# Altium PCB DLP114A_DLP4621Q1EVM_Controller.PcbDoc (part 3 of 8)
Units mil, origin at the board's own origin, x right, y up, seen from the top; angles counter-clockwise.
Board outline 4803.15 x 2598.43 mil, 14 copper layers (Top Layer, GND 1, SIGNAL 1, GND 2, SIGNAL 2, PWR SPLIT PLANE 1, GND 3, GND 4, PWR SPLIT PLANE 2, SIGNAL 3, GND 5, SIGNAL 4, GND 6, Bottom Layer), stack 91.4 mil thick; 489 components, 394 nets, 1925 pads, 1273 vias.
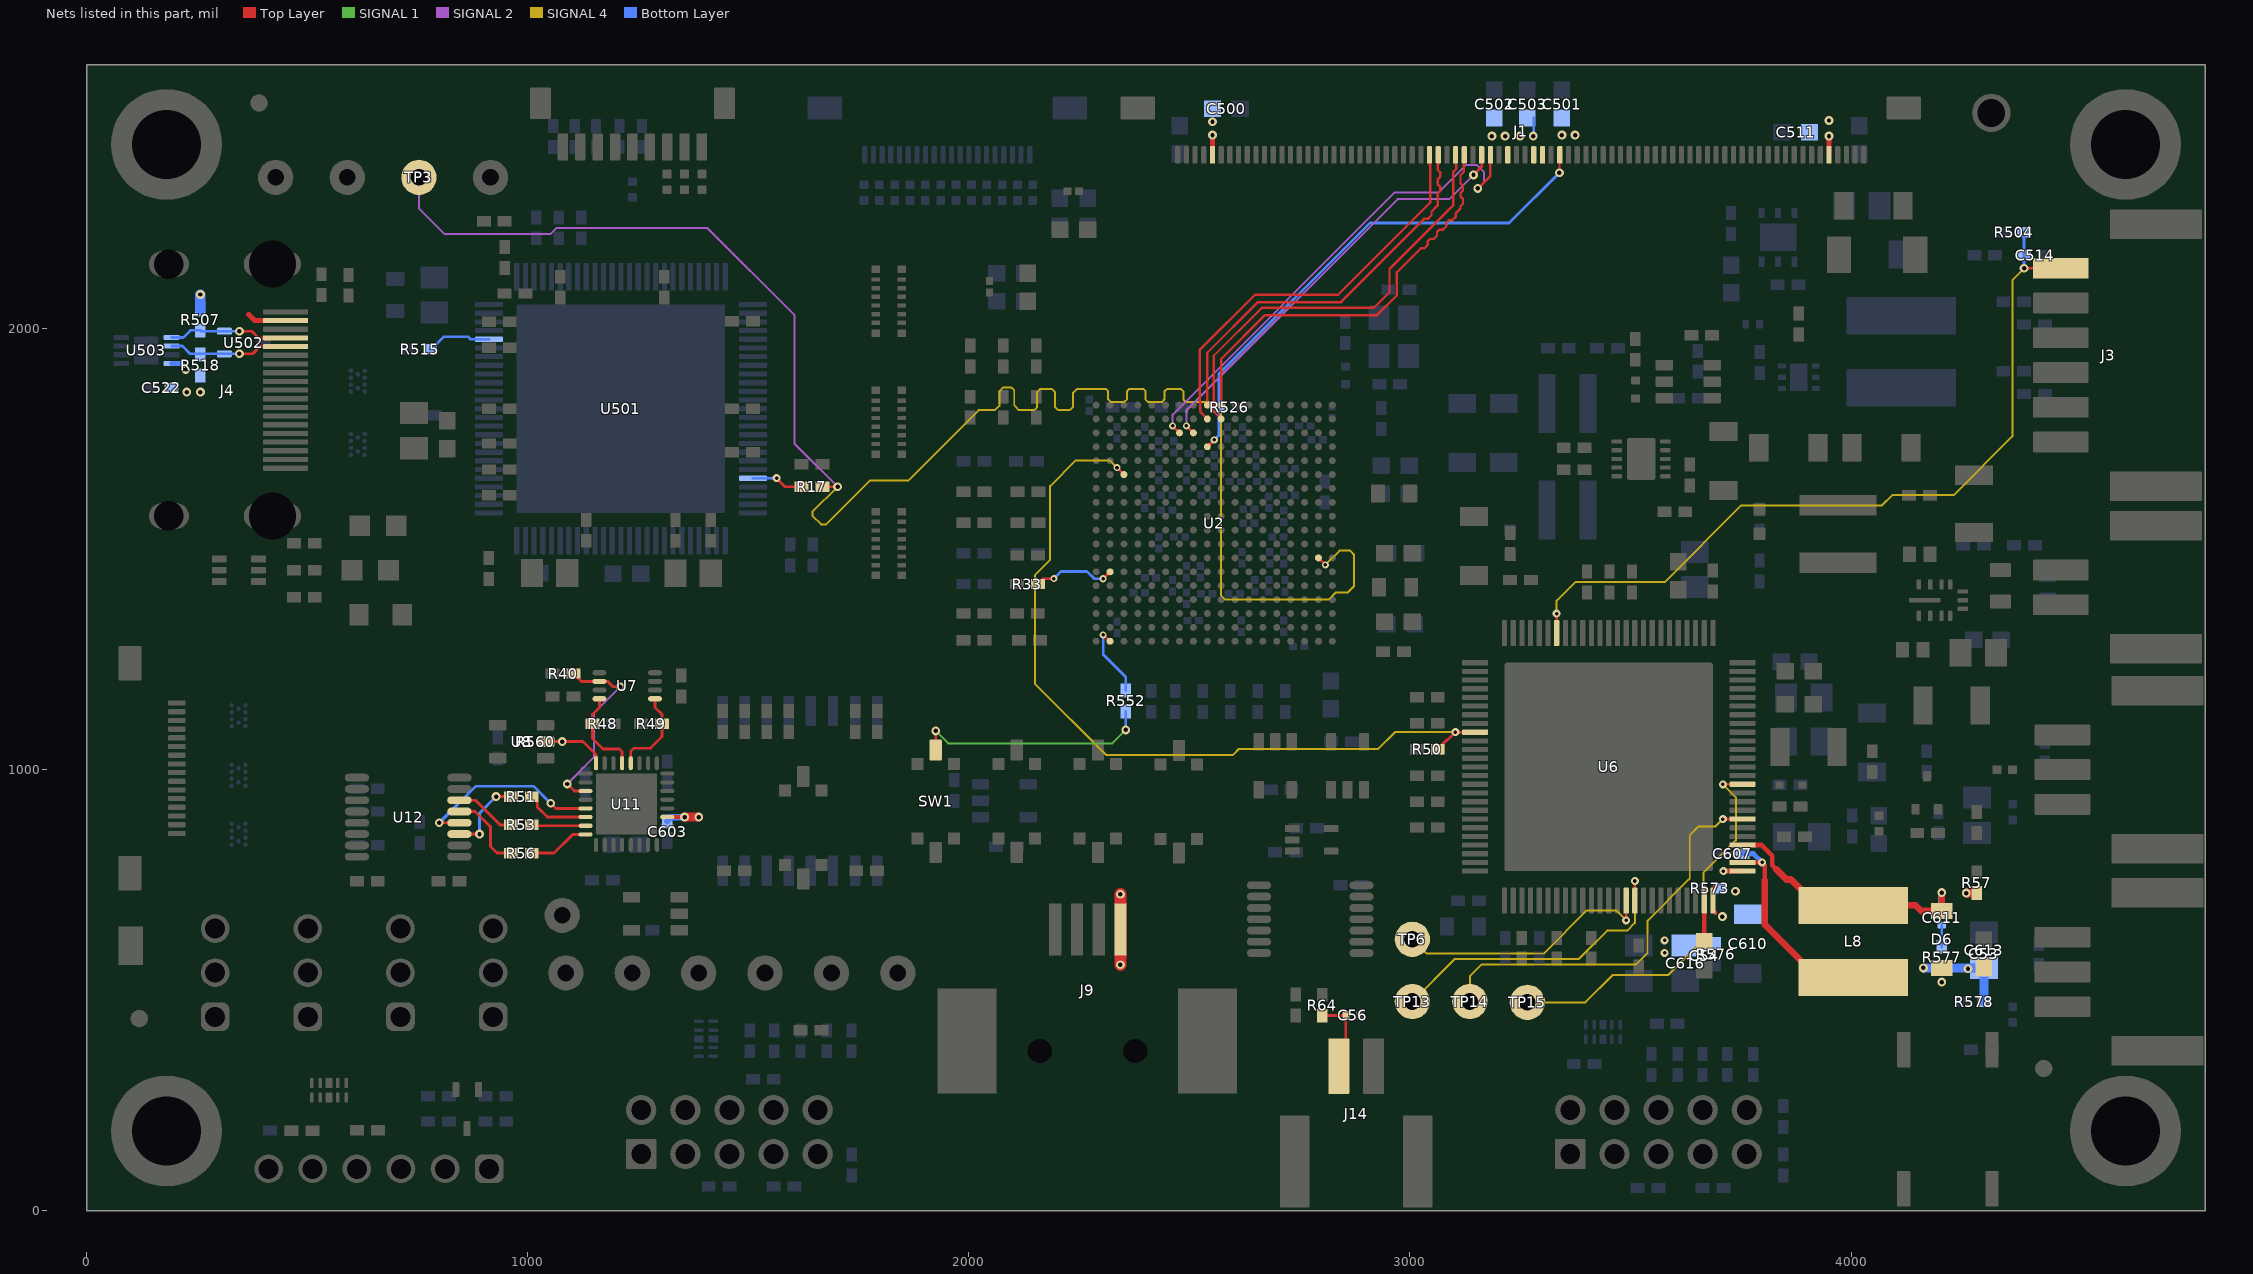
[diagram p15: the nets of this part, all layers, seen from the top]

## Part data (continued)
D4: library part CMP-0095628-1, "Red 631nm LED Indication - Discrete 2V 0805 (2012 Metric)", Color=Red, Digikey Part Number=160-1427-1-ND, Forward Current=20mA, Manufacturer=Lite-On, Mouser Part Number=859-LTST-C171KRKT, Operating Temperature Range="-55°C to +85°C", Power_TotalModule=75mW
D5: library part CMP-0095722-1, "Zener Diode 6.2 V 500 mW ±6.5% Surface Mount SOD-523", Digikey Part Number=SZMM5Z6V2T1GOSCT-ND, Manufacturer=onsemi, Max Reverse Leakage Current=3uA, Mouser Part Number=863-SZMM5Z6V2T1G, Operating Temperature Range="-65°C to +150°C", Power_W=500mW
D6: library part CMP-0028526-2, "Diode, Schottky, 40 V, 0.5 A, SOD-123", Manufacturer="ON Semiconductor", Value1=0.5A, Value2=0.51V
"ESD Susceptible1": library part CMP-0074840-1, "ESD Susceptible Symbol"
FB1 FB2 FB3 FB500: library part CMP-0086567-1, "FERRITE BEAD 120 OHM 0402 1LN", Manufacturer=TDK
FID1 FID2 FID3 FID4 FID5 FID6: library part CMP-0077181-1, "Fiducial mark.  There is nothing to buy or mount.", Manufacturer=N/A
J1: library part CMP-0095889-1, "80 Position FFC, FPC Connector Contacts, Bottom 0.020\" (0.50mm) Surface Mount, Right Angle", Current_A=500mA, Digikey Part Number=WM11298CT-ND, Manufacturer=Molex, Mouser Part Number=538-505110-8091, Operating Temperature Range="-40°C to +105°C", Voltage_V=50V
J2: library part CMP-0096269-1, "Connector Header Surface Mount 9 position 0.039\" (1.00mm)", Current_A=1A, Digikey Part Number=23-5013310907CT-ND, Manufacturer=Molex, Mouser Part Number=538-501331-0907, Operating Temperature Range="-40°C to +105°C", Voltage_V=100V
J3: library part CMP-0086751-1, "CONN HEADER SMD R/A 6POS 2MM", Current_A=3A, Manufacturer=Molex, Voltage_V=125V
J4: library part CMP-0095855-1, "HDMI 2.1 Receptacle Connector 19 Position Surface Mount, Right Angle; Through Hole", Current_A=500mA, Digikey Part Number=2223-HD04-19-TH-TRCT-ND, Manufacturer="CUI Devices", Mouser Part Number=179-HD04-19-TH-TR, Operating Temperature Range="-20°C to +85°C", Voltage_V=40V
J5: library part CMP-0089653-1, "Connector Header Surface Mount, Right Angle 2 position 0.079\" (2.00mm)", Current_A=3A, Digikey Part Number=WM7169CT-ND, Manufacturer=Molex, Mouser Part Number=538-502352-0200, Operating Temperature Range="-40°C to +105°C", Voltage_V=125V
J6: library part CMP-0086503-1, "CONN FPC BOTTOM 16POS .5MM R/A", Current_A=0.5A, Manufacturer=Molex, Voltage_V=50V
J7 J8: library part CMP-0055291-1, "Header(shrouded), 2mm, 3x1, Tin, R/A, SMT", Color=Natural, Current_A=3A, Manufacturer=Molex, Supplier Part Number 1=WM10858CT-ND, Voltage_V=125V
J9: library part CMP-0054924-1, "Connector, Receptacle, USB TYPE B, R/A, Top Mount SMT", Manufacturer="TE Connectivity", Supplier Part Number 1=A114945-ND
J10 J11 J12 J13: library part CMP-0054796-4, "Header, 2.54 mm, 3x1, Gold, TH", Manufacturer="Wurth Elektronik", Supplier Part Number 1=732-5316-ND
J14: library part CMP-0087312-1, "CONN HEADER SMD R/A 2POS 2MM", Current_A=3A, Manufacturer=Molex, Voltage_V=125V
J15 J16: library part CMP-0089821-1, "Connector Header Through Hole 10 position 0.100\" (2.54mm)", Current_A=2.5A, Digikey Part Number=WM9220-ND, Manufacturer=Molex, Mouser Part Number=538-70246-1002, Operating Temperature Range="-55°C to +120°C", Voltage_V=250V
J17: library part CMP-0054801-2, "Header, 2.54 mm, 6x1, Gold, TH", Color=Black, Manufacturer="Wurth Elektronik", Supplier Part Number 1=732-5319-ND
J500: library part CMP-0089654-1, "Easy-On FFC/FPC Connector 0.50mm Pitch, FD19 Series, Right-Angle, Bottom Contact, 1.90mm Height, 20 Circuits, Gold over Nickel Plating", Current_A=500mA, Digikey Part Number=WM11287CT-ND, Manufacturer=Molex, Mouser Part Number=538-505110-2091, Operating Temperature Range="-40°C to +105°C", Voltage_V=50V
L1 L3 L4 L514: library part CMP-0003086-1, "Ferrite Bead, 600 ohm @ 100 MHz, 0.5 A, 0805", Manufacturer="Wurth Elektronik", Supplier Part Number 1=732-1605-1-ND, Value1="0.3 ohm", Value2=0.5A, ValueDisplayed="600 ohm"
L2: library part CMP-0061651-2, "Inductor, Shielded, Composite, 22 uH, 3.4 A, 0.1 ohm, SMD", Manufacturer=Coilcraft, Value1="0.1 ohm", Value2=3.4A, ValueDisplayed=22uH
L5: library part CMP-0089947-1, "100 Ohms @ 100MHz 1 Power Line Ferrite Bead 0805 (2012 Metric) 4A 20mOhm", Digikey Part Number=445-172903-1-ND, Impedance At Frequency="100Ω @ 100MHz", Manufacturer=TDK, Mouser Part Number=810-MPZ2012S101ATD25, Operating Temperature Range="-55°C to +125°C", Test Frequency=100MHz, Tolerance_%=25%
L6 L7 L500 L501 L502 L503 L504 L505 L506 L507 L508 L509 L510 L511 L525 L526: library part CMP-0086567-1, "FERRITE BEAD 120 OHM 0402 1LN", Manufacturer=TDK, PartNumber=MMZ1005Y121CTD25
L8 L516: library part CMP-0062263-1, "Inductor, Shielded Drum Core, Ferrite, 10 uH, 1.2 A, 0.124 ohm, SMD", Manufacturer=Sumida, Supplier Part Number 1=308-1479-1-ND, Value1="0.124 ohm", Value2=1.2A, ValueDisplayed=10uH
L512 L513 L515 L517 L519 L521 L522 L523 L524: library part CMP-0003154-1, "Ferrite Bead, 110 ohm @ 100 MHz, 4.1 A, 0603", Manufacturer="Wurth Elektronik", Supplier Part Number 1=732-6116-1-ND, Value1="0.0145 ohm", Value2=4.1A, ValueDisplayed="110 ohm"
L518 L520: library part CMP-0061150-1, "Inductor, Shielded, Composite, 2.2 uH, 3.7 A, 0.02 ohm, SMD", Manufacturer=Coilcraft, Supplier Part Number 1=994-XFL4020-222MEB, Value1="0.02 ohm", Value2=3.7A, ValueDisplayed=2.2uH
Logo1: library part CMP-0074838-1, "Texas Instrument Corporate Signature"
Logo2: library part CMP-0074847-1, "FCC_disclaimer"
Logo3: library part CMP-0074844-1
Logo4: library part CMP-0074769-1
MH1 MH2 MH3 MH4: library part CMP-0078422-2, "PCB Mounting Hole", Manufacturer=Any, PartNumber=N/A
Q1: library part CMP-0000642-2, "MOSFET, N-CH, 30 V, 0.35 A, AEC-Q101, SOT-323", Alternate Manufacturer=None, Manufacturer=Nexperia, Supplier Part Number 1=568-10498-1-ND, Value1=1, Value2="0.52 nC"
R1 R2 R3 R5 R6 R7 R8 R13 R14 R16 R18 R20 R21 R22 R23 R26 R28 R29 R30 R33 R35 R40 R41 R42 R43 R45 R47 R48 R49 R52 R54 R59 R60 R61 R63 R65 R501 R502 R503 R505 R510 R511 R512 R515 R529 R533 R536 R537 R542 R543 R545 R547 R548 R550 R551 R559 R560 R561 R569 R570 R571 R572 R574 R575 R579 R580 R584 R590 R591: library part CMP-0026994-4, "RES, 10 k, 5%, 0.1 W, AEC-Q200 Grade 0, 0402", Manufacturer=Panasonic, Power_W=100mW, Supplier Part Number 1=P10KJCT-ND, TempCo="200 ppm/C", Tolerance_%=5%, Value2=0.1W, Value_Code=10k0, ValueDisplayed=10k
R4 R565: library part CMP-0026658-1, "RES, 10.0 k, 1%, 0.1 W, 0402", Manufacturer=Panasonic, Power_W=100mW, Supplier Part Number 1=P10.0KLCT-ND, TempCo="100 ppm/C", Tolerance_%=1%, Value2=0.1W, Value_Code=10k0, ValueDisplayed=10.0k
R9: library part CMP-0090161-1, "300 Ohms ±1% 0.1W, 1/10W Chip Resistor 0402 (1005 Metric) Automotive AEC-Q200 Thick Film", Digikey Part Number=P300LCT-ND, Manufacturer=Panasonic, Mouser Part Number=667-ERJ-2RKF3000X, Operating Temperature Range="-55°C to +155°C", Part Number=ERJ-2RKF3000X, Power_W=100mW, TempCo=100ppm/°C, Tolerance_%=1%
R10 R11 R12 R15 R17 R19 R36 R39 R51 R53 R56 R62 R64 R521 R522 R523 R530 R532 R538 R539 R546 R555 R564 R567 R568: library part CMP-0026696-1, "RES, 33.0, 1%, 0.1 W, 0402", Manufacturer=Panasonic, Power_W=100mW, Supplier Part Number 1=P33.0LCT-ND, TempCo="100 ppm/C", Tolerance_%=1%, Value2=0.1W, Value_Code=33R0, ValueDisplayed=33.0
R24: library part CMP-0026669-1, "RES, 150 k, 1%, 0.1 W, AEC-Q200 Grade 0, 0402", Manufacturer=Panasonic, Power_W=100mW, Supplier Part Number 1=P150KLCT-ND, TempCo="100 ppm/C", Tolerance_%=1%, Value2=0.1W, Value_Code=150k, ValueDisplayed=150K
R25 R31 R34: library part CMP-0026022-3, "RES, 150, 1%, 0.063 W, AEC-Q200 Grade 0, 0402", Manufacturer=Vishay-Dale, Power_W=63mW, Supplier Part Number 1=541-150LCT-ND, TempCo="100 ppm/C", Tolerance_%=1%, Value2=0.063W, Value_Code=150R, ValueDisplayed=150
R27 R46 R50 R531 R554 R558 R577 R592 R593: library part CMP-0026071-3, "RES, 1.00 k, 1%, 0.063 W, AEC-Q200 Grade 0, 0402", Manufacturer=Vishay-Dale, Power_W=63mW, Supplier Part Number 1=541-1.00KLCT-ND, TempCo="100 ppm/C", Tolerance_%=1%, Value2=0.063W, Value_Code=1k00, ValueDisplayed=1.00k
R32 R514: library part CMP-0026723-1, "RES, 180 k, 1%, 0.063 W, 0402", Manufacturer="Yageo America", Power_W=63mW, Supplier Part Number 1=311-180KLRCT-ND, TempCo="100 ppm/C", Tolerance_%=1%, Value2=0.063W, Value_Code=180k
R37 R38 R507 R518 R526 R549 R552 R553 R556 R557 R585: library part CMP-0026890-5, "RES, 2.2 k, 5%, 0.063 W, AEC-Q200 Grade 0, 0402", Manufacturer=Vishay-Dale, Power_W=63mW, Supplier Part Number 1=541-2.2KJCT-ND, TempCo="200 ppm/C", Tolerance_%=5%, Value2=0.063W, Value_Code=2k20, ValueDisplayed=2.2k
R44 R58: library part CMP-0026918-5, "RES, 3.3 k, 5%, 0.063 W, AEC-Q200 Grade 0, 0402", Manufacturer=Vishay-Dale, Power_W=63mW, Supplier Part Number 1=541-3.3KJCT-ND, TempCo="200 ppm/C", Tolerance_%=5%, Value2=0.063W, Value_Code=3k30, ValueDisplayed=3.3k
R55: library part CMP-0081723-1, "RES, 18.0 k, 1%, 0.1 W, AEC-Q200 Grade 0, 0402", Manufacturer=Panasonic, Power_W=100mW, Supplier Part Number 1=P18.0KLCT-ND, TempCo="100 ppm/C", Tolerance_%=1%, Value2=0.1W, Value_Code=18k0, ValueDisplayed=18.0k
R57: library part CMP-0025963-3, "RES, 10.0, 1%, 0.063 W, AEC-Q200 Grade 0, 0402", Manufacturer=Vishay-Dale, Power_W=63mW, Supplier Part Number 1=541-10.0LCT-ND, TempCo="100 ppm/C", Tolerance_%=1%, Value2=0.063W, Value_Code=10R0, ValueDisplayed=10.0
R500 R524 R534: library part CMP-0081856-1, "RES, 0, 0%, 0.2 W, AEC-Q200 Grade 0, 0402", Manufacturer=Vishay-Dale, Power_W=200mW, Supplier Part Number 1=541-0.0YBTR-ND, Tolerance_%=0%, Value2=0.2W, Value_Code=0
R504 R506 R519: library part CMP-0026517-2, "RES, 6.81 k, 1%, 0.063 W, AEC-Q200 Grade 0, 0402", Manufacturer=Vishay-Dale, Power_W=63mW, Supplier Part Number 1=541-6.81KLCT-ND, TempCo="100 ppm/C", Tolerance_%=1%, Value2=0.063W, Value_Code=6k81, ValueDisplayed=6.81k
R508 R544: library part CMP-0026379-2, "RES, 43.2 k, 1%, 0.063 W, AEC-Q200 Grade 0, 0402", Manufacturer=Vishay-Dale, Power_W=63mW, Supplier Part Number 1=541-43.2KLCT-ND, TempCo="100 ppm/C", Tolerance_%=1%, Value2=0.063W, Value_Code=43k2, ValueDisplayed=43.2k
R509: library part CMP-0026100-2, "RES, 1.00 M, 1%, 0.063 W, AEC-Q200 Grade 0, 0402", Manufacturer=Vishay-Dale, Power_W=63mW, Supplier Part Number 1=541-1.00MLCT-ND, TempCo="100 ppm/C", Tolerance_%=1%, Value2=0.063W, Value_Code=1M00, ValueDisplayed=1.00M
R513: library part CMP-0860333-1, "RES, 360 k, 1%, 0.1 W, AEC-Q200 Grade 0, 0402", Manufacturer=Panasonic, Power_W=100mW, TempCo="100 ppm/C", Tolerance_%=1%, Value2=0.1W, Value_Code=360k, ValueDisplayed=360K
R516: library part CMP-0026434-2, "RES, 4.99, 1%, 0.063 W, AEC-Q200 Grade 0, 0402", Manufacturer=Vishay-Dale, Power_W=63mW, Supplier Part Number 1=541-4.99LLCT-ND, TempCo="100 ppm/C", Tolerance_%=1%, Value2=0.063W, Value_Code=4R99, ValueDisplayed=4.99
R517: library part CMP-0026463-2, "RES, 5.11 k, 1%, 0.063 W, AEC-Q200 Grade 0, 0402", Manufacturer=Vishay-Dale, Power_W=63mW, Supplier Part Number 1=541-5.11KLCT-ND, TempCo="100 ppm/C", Tolerance_%=1%, Value2=0.063W, Value_Code=5k11, ValueDisplayed=5.11k
R520: library part CMP-0090071-1, "Res Thick Film 0402 3K Ohm 1% 0.1W(1/10W) +/-100ppm/C Molded SMD Automotive Punched T/R", Digikey Part Number=P3.00KLCT-ND, Manufacturer=Panasonic, Mouser Part Number=667-ERJ-2RKF3001X, Operating Temperature Range="-55°C to +155°C", Part Number=ERJ-2RKF3001X, Power_W=100mW, TempCo=100ppm/°C, Tolerance_%=1%
R525 R527 R528: library part CMP-0026375-2, "RES, 42.2 k, 1%, 0.063 W, AEC-Q200 Grade 0, 0402", Manufacturer=Vishay-Dale, Power_W=63mW, Supplier Part Number 1=541-42.2KLCT-ND, TempCo="100 ppm/C", Tolerance_%=1%, Value2=0.063W, Value_Code=42k2, ValueDisplayed=42.2k
R535 R573: library part CMP-0026995-1, "RES, 100 k, 5%, 0.1 W, AEC-Q200 Grade 0, 0402", Manufacturer=Panasonic, Power_W=100mW, Supplier Part Number 1=P100KJCT-ND, TempCo="200 ppm/C", Tolerance_%=5%, Value2=0.1W, Value_Code=100k
R540: library part CMP-0026435-2, "RES, 511 k, 1%, 0.063 W, AEC-Q200 Grade 0, 0402", Manufacturer=Vishay-Dale, Power_W=63mW, Supplier Part Number 1=541-511KLCT-ND, TempCo="100 ppm/C", Tolerance_%=1%, Value2=0.063W, Value_Code=511k
R541: library part CMP-0026670-1, "RES, 154 k, 1%, 0.1 W, AEC-Q200 Grade 0, 0402", Manufacturer=Panasonic, Power_W=100mW, Supplier Part Number 1=P154KLCT-ND, TempCo="100 ppm/C", Tolerance_%=1%, Value2=0.1W, Value_Code=154k
R562: library part CMP-0026996-2, "RES, 20 k, 5%, 0.1 W, AEC-Q200 Grade 0, 0402", Manufacturer=Panasonic, Power_W=100mW, Supplier Part Number 1=P20KJCT-ND, TempCo="200 ppm/C", Tolerance_%=5%, Value2=0.1W, Value_Code=20k0, ValueDisplayed=20k
R563: library part CMP-0078244-2, "RES, 30.0 k, 1%, 0.063 W, AEC-Q200 Grade 0, 0402", Manufacturer=Vishay-Dale, Power_W=63mW, Supplier Part Number 1=541-30.0KLCT-ND, TempCo="100 ppm/C", Tolerance_%=1%, Value2=0.063W, Value_Code=30k0, ValueDisplayed=30.0k
R566: library part CMP-0026035-3, "RES, 162, 1%, 0.063 W, AEC-Q200 Grade 0, 0402", Manufacturer=Vishay-Dale, Power_W=63mW, Supplier Part Number 1=541-162LCT-ND, TempCo="100 ppm/C", Tolerance_%=1%, Value2=0.063W, Value_Code=162R, ValueDisplayed=162
R576 R578: library part CMP-0026437-2, "RES, 51.1 k, 1%, 0.063 W, AEC-Q200 Grade 0, 0402", Manufacturer=Vishay-Dale, Power_W=63mW, Supplier Part Number 1=541-51.1KLCT-ND, TempCo="100 ppm/C", Tolerance_%=1%, Value2=0.063W, Value_Code=51k1, ValueDisplayed=51.1k
R581 R582 R583 R586 R587 R588 R589: library part CMP-0026544-2, "RES, 75.0, 1%, 0.063 W, AEC-Q200 Grade 0, 0402", Manufacturer=Vishay-Dale, Power_W=63mW, Supplier Part Number 1=541-75.0LCT-ND, TempCo="100 ppm/C", Tolerance_%=1%, Value2=0.063W, Value_Code=75R0, ValueDisplayed=75.0
RN1 RN2 RN3: library part CMP-0015347-2, "RES, 33, 5%, 0.0625 W, Resistor Array - 8x1", Manufacturer=Panasonic, Power_W=62.5mW, Supplier Part Number 1=Y1330CT-ND, TempCo="200 ppm/C", Tolerance_%=5%, Value2=0.0625W, Value_Code=33R0, ValueDisplayed=33
SW1 SW2 SW3 SW4 SW5: library part CMP-0095685-1, "Switch Slide OFF ON SPST Recessed Slide 0.1A 24VDC Gull Wing SMD Embossed T/R", Coil Resistance_ohm=200mΩ, Contact Current Rating=100mA, Digikey Part Number=563-1192-1-ND, Manufacturer="Nidec Copal", Mouser Part Number=229-CVS-01TB, Operating Temperature Range="-40°C to +85°C"
SW6: library part CMP-0095672-1, "Toggle Switch SPST Surface Mount, Right Angle", Coil Resistance_ohm=50mΩ, Manufacturer="C&K Components", Mouser Part Number=611-GT12MSABETR, Operating Temperature Range="-30°C to +85°C"
TP1 TP2 TP3 TP4 TP5 TP6 TP7 TP8 TP9 TP10 TP11 TP12 TP13 TP14 TP15: library part CMP-0078143-2, "TEST POINT.  No entry in BOM.", Manufacturer=N/A
TP16: library part CMP-0003968-1, "Test Point, SMT", Manufacturer=Harwin, Supplier Part Number 1=952-2664-1-ND
TP17: library part CMP-0055144-2, "Test Point, Compact, White, TH", Color=White, Manufacturer="Keystone Electronics", Supplier Part Number 1=36-5007-ND
U1: library part CMP-0081996-1, "5.5V, 2A, 52mΩ Automotive High-Side Load Switch with Adjustable Rise Time & Quick Output Discharge, DBV0006A (SOT-23-6)", Alternate Manufacturer="Texas Instruments", Alternate PartNumber=TPS22918TDBVTQ1, Operating Temperature Range="-40 to 105 C", Rating=Automotive
U2: library part CMP-0096130-1, Manufacturer="Texas Instruments", Operating Temperature Range=to
U3: library part CMP-0074044-5, "Automotive 2.5V to 6V, 2.25MHz Fixed Frequency Dual (1A/600mA) Buck Converter with 1-Wire Interface, DRC0010J (VSON-10)", Manufacturer="Texas Instruments", Operating Temperature Range="-40 to 125 C", Rating=Automotive
U4: library part CMP-0051776-3, "Automotive Catalog Dual Inverter Buffer/Driver with Open-Drain Output, DCK0006A (SOT-SC70-6)", F @ Nom Voltage(Max)(Mhz)=150, Generic Part Number=SN74LVC2G06-Q1, ICC @ Nom Voltage(Max)(mA)=0.01, Manufacturer="Texas Instruments", Operating Temperature Range="-40 to 125 C", Rating=Automotive, tpd @ Nom Voltage(Max)(ns)=7.2,3.9,3.4,2.9, Voltage(Nom)(V)=1.8,2.5,3.3,5
U5: library part CMP-0860015-2, "LMR342XX-Q1 SIMPLE SWITCHER® 42 V, 600mA/1.5A Synchronous Buck Converter, RNX0012B (VQFN-HR-12)", Alternate Manufacturer="Texas Instruments"
U6: library part CMP-0750180-3, "DLP® System Management and Illumination Controller for DLP553x-Q1 Chipset, PZP0100K (TQFP-100)", Alternate Manufacturer="Texas Instruments", Operating Temperature Range="-40 to 105 C", Rating=Automotive
U7: library part CMP-0051205-2, "Automotive 2-Bit Bidirectional Voltage-Level Translator for Open-Drain and Push-Pull Application, DCU0008A (VSSOP-8)", Generic Part Number=TXS0102-Q1, ICC @ Nom Voltage(Max)(mA)=0.012, Manufacturer="Texas Instruments", Operating Temperature Range="-40 to 125 C", Rating=Automotive, tpd @ Nom Voltage(Max)(ns)=4.2, Voltage(Nom)(V)=3.3
U8 U15: library part CMP-0051394-2, "Automotive Catalog Single Buffer/Driver With Open-Drain Output, DBV0005A (SOT-23-5)", F @ Nom Voltage(Max)(Mhz)=150, Generic Part Number=SN74LVC1G07-Q1, ICC @ Nom Voltage(Max)(mA)=0.01, Manufacturer="Texas Instruments", Operating Temperature Range="-40 to 125 C", Rating=Automotive, tpd @ Nom Voltage(Max)(ns)=9.8,7,5.7,4.9, Voltage(Nom)(V)=1.8,2.5,3.3,5
U9 U10 U510: library part CMP-0050954-2, "Automotive Catalog Low-Voltage Single FET Bus Switch, DBV0005A (SOT-23-5)", F @ Nom Voltage(Max)(Mhz)=200, Generic Part Number=SN74CBTLV1G125-Q1, ICC @ Nom Voltage(Max)(mA)=0.01, Manufacturer="Texas Instruments", Operating Temperature Range="-40 to 125 C", Rating=Automotive, tpd @ Nom Voltage(Max)(ns)=0.25, Voltage(Nom)(V)=3.3
U11: library part CMP-0086752-1, "USB Bridge, USB to I²C USB 2.0 UART Interface 32-QFN (5x5)", Manufacturer=Cypress
U12: library part CMP-0066451-2, "4-Bit Dual-Supply Bus Transceiver With Configurable Voltage-Level Shifting and 3-State Outputs, PW0016A (TSSOP-16)", Alternate Manufacturer="Texas Instruments", Alternate PartNumber=SN74AVC4T774PW, Operating Temperature Range="-40 to 85 C", Rating=Catalog
U13: library part CMP-0051661-3, "Automotive Catalog Single Inverter, DCK0005A, LARGE T&R", F @ Nom Voltage(Max)(Mhz)=150, Generic Part Number=SN74LVC1G04-Q1, ICC @ Nom Voltage(Max)(mA)=0.01, Manufacturer="Texas Instruments", Operating Temperature Range(C)="-40 to 125", Rating=Automotive, tpd @ Nom Voltage(Max)(ns)=7.5,5.2,4.2,3.7, Voltage(Nom)(V)=1.8,2.5,3.3,5
U14: library part CMP-0054515-1, "Automotive Catalog Quadruple 2-Input Positive-AND Gate, PW0014A, LARGE T&R", F @ Nom Voltage(Max)(Mhz)=70, Generic Part Number=SN74LVC08A-Q1, ICC @ Nom Voltage(Max)(mA)=0.01, Manufacturer="Texas Instruments", Operating Temperature Range(C)="-40 to 125", Rating=Automotive, tpd @ Nom Voltage(Max)(ns)=4.8,4.1, Voltage(Nom)(V)=2.7,3.3
U16 U502: library part CMP-0073595-1, "Automotive Dual-Channel High-Speed ESD Protection Device, DCK0003A (SOT-SC70-3)", Alternate Manufacturer="Texas Instruments"
U17 U512 U513: library part CMP-0073599-3, "Automotive 4-Channel ESD Protection Solution for SuperSpeed (up to 5 Gbps) Interface, DQA0010A (USON-10)", Alternate Manufacturer="Texas Instruments"
U500: library part CMP-0070711-3, "500mA Low Dropout CMOS Linear Regulators Stable with Ceramic Output Capacitors, 6-pin LLP, Pb-Free, 1000 Reel", Manufacturer="Texas Instruments", PackageTopMarking=ZXYTT*L130B, PowerWise=Y
U501: library part CMP-0095606-2, "Digital Receiver 3RX 100-Pin HTQFP EP T/R", Digikey Part Number=296-35476-1-ND, Manufacturer="Texas Instruments", Max Supply Voltage=3.6V, Min Supply Voltage=3V, Mouser Part Number=595-TFP401AIPZPRQ1, Operating Temperature Range="-40°C to +85°C"
U503: library part CMP-0095877-1, "EEPROM Memory IC 2Kb (256 x 8) I²C 1 MHz 8-UDFN (2x3)", Digikey Part Number=AT34C02D-MAHM-TCT-ND, Frequency_Fixed=1MHz, Manufacturer="Microchip Technology", Max Supply Voltage=5.5V, Min Supply Voltage=1.7V, Mouser Part Number=556-AT34C02D-MAHM-T, Nominal Supply Current=1-2mA, Operating Temperature Range="-40°C to +85°C"
U504: library part CMP-0074076-5, "Automotive Catalog 1.2A Switch, High Voltage Boost Converter in 2x2mm QFN Package, DRV0006A (WSON-6)", Alternate Manufacturer="Texas Instruments"
U505 U506 U507 U509 U511: library part CMP-0095720-1, "Common-mode EMI filter for differential channels with ESD protection", Digikey Part Number=1727-2506-1-ND, Manufacturer=Nexperia, Mouser Part Number=771-PCMF2HDMI2SZ, Operating Temperature Range=to
U508: library part CMP-0086504-1, "FLASH - NOR Memory IC 128Mb (16M x 8) SPI 133MHz  16-SOP2", Manufacturer=Micron
Y500: library part CMP-0087311-1, "SMD SEAM SEALING X'TAL 3.2×2.5", Frequency Stability=50ppm, Frequency Tolerance=10ppm, Frequency_Fixed=16MHz, Load Capacitance=10pF, Manufacturer="TXC Corporation"
ZZ1: library part CMP-0003616-3
ZZ2: library part CMP-0077236-1
ZZ3: library part CMP-0077237-1
ZZ4 ZZ5: library part CMP-0077238-1

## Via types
v1: diameter 20, hole 10, Top Layer to Bottom Layer, tented top, 716 vias
v2: diameter 16, hole 8, Top Layer to Bottom Layer, 234 vias
v3: diameter 19.68, hole 7.87, Top Layer to Bottom Layer, 170 vias
v4: diameter 18, hole 8, Top Layer to Bottom Layer, tented top, 78 vias
v5: diameter 18, hole 8, Top Layer to Bottom Layer, tented bottom, 51 vias
v6: diameter 39.37, hole 19.68, Top Layer to Bottom Layer, 24 vias

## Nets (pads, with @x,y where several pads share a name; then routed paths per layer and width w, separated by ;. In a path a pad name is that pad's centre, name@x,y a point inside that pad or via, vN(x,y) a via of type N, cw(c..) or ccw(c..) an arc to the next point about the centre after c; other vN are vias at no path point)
AMUX0: TP15.1 U6.61 | length 897.9
  Top Layer w6.3: v4(3709.3,966.95) U6.61@3753.82,966.95
  SIGNAL 4 w4.5: TP15.1@3266.08,472.65 3397.43,472.65 3459.45,534.67 3585.74,534.67 3665.13,614.06 3665.13,766.1 3738.89,839.86 3738.89,937.35 v4(3709.3,966.95)
AMUX1: TP14.1 U6.57 | length 923.9
  Top Layer w6.3: v4(3709.3,888.21) U6.57@3753.82,888.21
  SIGNAL 4 w4.5: TP14.1@3135.69,474.4 3135.69,532.16 3161.87,558.34 3512.18,558.34 3538.85,585.01 3538.85,657.78 3632.35,751.28 3634.2,753.14 3634.2,851.88 3653.62,871.3 3692.39,871.3 v4(3709.3,888.21)
BLUE_LED_THERM: C514.1 J3.6 R504.1 U6.94 | length 1817.6
  Top Layer w6.3: U6.94@3332.56,1309.47 v4(3332.56,1353.99) ; v1(4392.2,2136.65) J3.6@4475.2,2136.65
  SIGNAL 4 w4.5: v4(3332.56,1353.99) 3332.56,1383.11 3374.85,1425.4 3577.65,1425.4 3751.44,1599.19 4070.05,1599.19 4093.44,1622.59 4232.62,1622.59 4365.6,1755.57 4365.6,2110.05 v1(4392.2,2136.65)
  Bottom Layer w6.3: v1(4392.2,2136.65) C514.1@4392.2,2166.65 R504.1@4392.2,2218.21
CHKSUM_SEL: R552.1 U2.V2 | length 168
  Top Layer w6.3: v2@2305.05,1305.72 U2.V2@2319.6,1291.17
  Bottom Layer w6.3: v2(2304.58,1305.72) 2304.58,1261.37 2329.72,1236.24 2355.62,1210.34 R552.1@2355.62,1179.45
CKS_PU: R552.2 SW1.1 | length 540.4
  Top Layer w6.3: SW1.1@1924.78,1044.67 v1(1924.78,1088.07)
  SIGNAL 1 w4.5: v1(1924.78,1088.07) 1952.97,1059.88 2325.18,1059.88 v1(2355.62,1090.32)
  Bottom Layer w6.3: v1(2355.62,1090.32) R552.2@2355.62,1132.21
CY_GPIO_7: R560.1 U8.2 U11.32 | length 183.2
  Top Layer w6.3: U8.2@1040.44,1063.12 1041.01,1063.69 1125.22,1063.69 1154.59,1034.33 U11.32@1154.59,1014.77
  Bottom Layer w6.3: R560.1@1041.01,1063.69 v1(1078.12,1063.69)
CY_GPIO_11: R51.1 U11.6 | length 147.5
  Top Layer w6.3: R51.1@1009.09,939.01 1021.61,926.49 1021.61,915.41 1044.42,892.61 U11.6@1130.85,892.61
CY_GPIO_12: R53.1 U11.7 | length 122.6
  Top Layer w6.3: R53.1@1009.09,874.98 1011.14,872.92 U11.7@1130.85,872.92
CY_GPIO_13: R56.1 U11.8 | length 139.3
  Top Layer w6.3: R56.1@1009.09,810.94 1059.81,810.94 1102.11,853.24 U11.8@1130.85,853.24
CY_HOST_I2C_OE: R40.2 U7.6 U11.3 | length 436
  Top Layer w6.3: v1(1089.7,967.63) 1105.66,951.66 U11.3@1130.85,951.66 ; R40.2@1103.81,1218.07 1121.65,1200.22 U7.6@1162.49,1200.22 1162.84,1199.88 1181.45,1199.88 1193.27,1188.06 v1(1209.54,1188.06)
  SIGNAL 2 w4.5: v1(1089.7,967.63) 1149.88,1027.81 1149.88,1128.4 v1(1209.54,1188.06)
CY_HOST_SCL: R49.1 U7.1 U11.28 | length 203.5
  Top Layer w6.3: U11.28@1233.33,1014.77 1233.33,1041.05 1241.1,1048.82 1278.08,1048.82 1304.11,1074.85 R49.1@1304.11,1104.45 1304.11,1125.64 1288.48,1141.27 U7.1@1288.48,1160.85
CY_HOST_SDA: R48.1 U7.8 U11.29 | length 201.9
  Top Layer w6.3: U7.8@1162.49,1160.85 1162.49,1141.15 1146.86,1125.52 R48.1@1146.86,1104.45 1146.86,1070.85 1170.76,1046.96 1207.73,1046.96 1213.64,1041.05 U11.29@1213.64,1014.77
CY_SPI_CLK: R56.2 U12.5 | length 182
  Top Layer w6.3: U12.5@845.06,905.25 880.81,905.25 915.29,870.77 915.29,826.06 930.41,810.94 R56.2@961.84,810.94
CY_SPI_CSZ: R53.2 U12.6 | length 139.9
  Top Layer w6.3: U12.6@845.06,930.84 881.78,930.84 937.64,874.98 R53.2@961.84,874.98
CY_SPI_PICO: R51.2 U12.3 | length 179.6
  Top Layer w6.3: U12.3@845.06,854.06 v1(890.62,854.06) ; v1(928.36,939.01) R51.2@961.84,939.01
  Bottom Layer w6.3: v1(890.62,854.06) 890.62,901.27 v1(928.36,939.01)
CY_SPI_POCI: U11.5 U12.4 | length 432.2
  Top Layer w6.3: v1(799.5,879.65) U12.4@845.06,879.65 ; v1(1052.02,924) 1063.73,912.29 U11.5@1130.85,912.29
  Bottom Layer w6.3: v1(799.5,879.65) 882.51,962.66 1013.36,962.66 v1(1052.02,924)
CY_VBUS: C603.1 J9.1 U11.19 | length 306.4
  Top Layer w9: U11.19@1316.13,892.61 v1(1355.65,892.61)
  Top Layer w20: v1(1355.65,892.61) v1(1387.51,892.61)
  Top Layer w27.5: v1(2343.51,557.96) J9.1@2343.51,637.8 v1(2343.51,717.63)
  Bottom Layer w15: C603.1@1316.13,883.02 1325.71,892.61 v1(1355.65,892.61) v1(1387.51,892.61)
DA_M_S: R33.2 U2.N2 | length 188.9
  Top Layer w6.3: R33.2@2156.43,1420.91 2168.66,1433.14 v2(2192.52,1433.14) ; v2(2304.32,1432.9) U2.N2@2320.07,1448.65
  Bottom Layer w6.3: v2(2192.52,1433.14) 2208.93,1449.55 2267.87,1449.55 2284.51,1432.9 v2(2304.32,1432.9)
DATAEN: R17.2 TP3.1 U2.M17 | length 3861.3
  Top Layer w6.3: R17.2@1667.85,1641.37 v1(1702.37,1641.37) ; U2.M17@2792.51,1480.15 v2(2808.26,1464.4)
  SIGNAL 4 w4.5: v1(1702.37,1641.37) 1645.28,1584.29 1645.28,1576.06 1665.03,1556.31 1676.7,1556.31 1776.47,1656.07 1863.27,1656.07 2022.33,1815.13 2059.14,1815.13 2065.92,1821.9 2069.55,1825.54 2069.55,1858.45 2077.03,1865.92 2097.03,1865.92 2102.92,1860.04 2102.92,1825.79 2106.3,1822.4 2113.58,1815.13 2121.58,1815.13 2147.92,1815.13 2154.69,1821.9 2154.69,1856.15 2161.97,1863.43 2188.31,1863.43 2195.08,1856.66 2195.08,1822.4 2202.36,1815.13 2228.69,1815.13 2236.55,1822.98 2236.55,1854.66 2245.32,1863.43 2310.31,1863.43 2315.96,1857.77 2315.96,1839.54 2321.46,1834.04 2352.74,1834.04 2358.66,1839.96 2358.66,1858.47 2363.62,1863.43 2394.9,1863.43 2400.82,1857.51 2400.82,1839 2406.32,1833.51 2437.6,1833.51 2443.52,1839.43 2443.52,1857.66 2449.29,1863.43 2480.57,1863.43 2486.49,1857.51 2486.49,1839.28 2492.27,1833.51 2546.62,1833.51 2572.03,1808.1 2572.03,1394.83 2581.09,1385.76 2815.46,1385.76 2831.41,1401.71 2859.34,1401.71 2873.13,1415.49 2873.13,1487.56 2864.17,1496.52 2840.4,1496.52 v2(2808.26,1464.4)
  SIGNAL 2 w4.5: TP3.1@753.33,2342.8 753.33,2272.66 812.02,2213.98 1050.74,2213.98 1064.7,2227.94 1407.57,2227.94 1604.22,2031.29 1604.22,1739.49 v1@1702.34,1641.37
DATAEN_S: R17.1 U501.46 | length 118.1
  Top Layer w6.3: v5(1564.12,1660.84) 1583.59,1641.37 R17.1@1620.61,1641.37
  Bottom Layer w6.3: U501.46@1510.53,1660.84 v5(1564.12,1660.84)
DDC_clock: J4.15 R518.1 U502.1 U503.6 | length 272.5
  Top Layer w6.3: v1(346.46,1942.84) 376.63,1942.84 392.9,1959.11 J4.15@451.18,1959.11
  Bottom Layer w6.3: U503.6@192.57,1960.21 217.12,1960.21 234.48,1942.84 257.96,1942.84 U502.1@312.41,1942.84 v1(346.46,1942.84)
DDC_data: J4.16 R507.1 U502.2 U503.5 | length 272.4
  Top Layer w6.3: v1(346.46,1994.03) 374.83,1994.03 390.07,1978.79 J4.16@451.18,1978.79
  Bottom Layer w6.3: U503.5@192.57,1979.89 219.64,1979.89 235.77,1996.03 R507.1@257.96,1996.03 259.96,1994.03 U502.2@312.41,1994.03 v1(346.46,1994.03)
DLPC230_RESETZ: R50.2 U2.F3 U6.9 | length 1809.1
  Top Layer w6.3: v2@2335.91,1684.7 U2.F3@2351.48,1669.12 ; R50.2@3062.87,1046.6 3083.37,1067.1 3085.03,1067.1 v4(3103,1085.06) U6.9@3147.52,1085.06
  SIGNAL 4 w4.5: v2(2335.82,1684.7) 2319.1,1701.42 2242.51,1701.42 2184.09,1642.99 2184.09,1475.47 2149.85,1441.23 2149.85,1194.72 2310.95,1033.63 2598.94,1033.63 2612.42,1047.11 2928.06,1047.11 2966.02,1085.06 v4(3103,1085.06)
DMD_DEN_ARSTZ: J1.36 R526.2 U2.D9 | length 1177.5
  Top Layer w5.3: v1(3338.78,2353.18) 3338.78,2392.8 J1.36@3339.68,2393.7
  Top Layer w6.3: U2.D9@2540.54,1732.12 v2(2556.29,1747.86)
  Bottom Layer w6.3: v2(2556.29,1747.86) 2566.29,1757.86 R526.2@2566.29,1821.42 2566.29,1896.4 2909.18,2239.28 3224.88,2239.28 v1(3338.78,2353.18)
DMD_LS0_CLK_N: J1.47 U2.A10 | length 972.3
  Top Layer w5.4: U2.A10@2572.04,1826.6 2572.04,1931.41 2671.18,2030.55 2925.3,2030.55 2970.31,2075.56 2970.31,2127.77 3024.44,2181.89 3032.42,2181.89 3039.96,2189.43 3039.96,2197.41 3045.61,2203.07 3053.6,2203.07 3061.13,2210.6 3061.13,2218.59 3066.79,2224.25 3074.78,2224.25 3082.31,2231.78 3082.31,2239.77 3087.97,2245.43 3095.96,2245.43 3103.49,2252.96 3103.49,2260.95 3114.56,2272.02 3114.56,2277.16 3120.21,2282.81 3120.21,2293.46 3114.56,2299.11 3114.56,2307.11 3120.21,2312.76 3120.21,2323.41 3114.56,2329.06 3114.56,2347.7 3121.71,2354.84 3121.71,2369.87 3123.15,2371.32 J1.47@3123.15,2393.7
DMD_LS0_CLK_P: J1.48 U2.B10 | length 982.7
  Top Layer w5.4: U2.B10@2572.04,1795.11 2556.29,1810.86 2556.29,1836.47 2555.24,1837.52 2555.24,1938.37 2664.22,2047.35 2918.34,2047.35 2953.51,2082.52 2953.51,2134.73 3097.76,2278.98 3097.76,2354.66 3104.91,2361.8 3104.91,2369.87 3103.46,2371.32 J1.48@3103.46,2393.7
DMD_LS0_RDATA: J1.44 U2.C7 | length 1125.7
  Top Layer w6.3: v2(2461.8,1779.36) U2.C7@2477.55,1763.61 ; v1(3153.77,2317.88) 3182.21,2346.32 J1.44@3182.2,2393.7
  SIGNAL 2 w4.5: v2(2461.8,1779.36) 2461.8,1804.73 2965.65,2308.58 3065.16,2308.58 3127.81,2371.22 3151.56,2371.22 3167.99,2354.8 3167.99,2332.1 v1(3153.77,2317.88)
DMD_LS0_WDATA_N: J1.50 U2.A9 | length 908.6
  Top Layer w5.4: U2.A9@2540.54,1826.6 2540.54,1945.29 2655.26,2060 2843.99,2060 3033.23,2249.25 3041.22,2249.25 3048.75,2256.78 3048.75,2264.77 3062.65,2278.66 3062.65,2305.68 3068.3,2311.33 3068.3,2321.98 3062.65,2327.63 3062.65,2338.28 3068.3,2343.93 3068.3,2354.58 3062.65,2360.23 3062.65,2369.87 3064.09,2371.32 J1.50@3064.09,2393.7
DMD_LS0_WDATA_P: J1.51 U2.B9 | length 933
  Top Layer w5.4: U2.B9@2540.54,1795.11 2524.79,1810.86 2524.79,1836.47 2523.74,1837.52 2523.74,1952.25 2648.3,2076.8 2837.03,2076.8 3045.85,2285.62 3045.85,2369.87 3044.41,2371.32 J1.51@3044.41,2393.7
DMD_LS1_RDATA: J1.45 U2.C8 | length 982.4
  Top Layer w6.3: v2(2493.3,1779.36) U2.C8@2509.05,1763.61 ; v1(3144.08,2348.48) 3162.52,2366.92 J1.45@3162.52,2393.7
  SIGNAL 2 w4.5: v2@2493.39,1779.46 2493.39,1815.11 2971.99,2293.7 3089.29,2293.7 v1(3144.08,2348.48)
DMD_VBIAS: C502.1 C610.1 J1.42 R573.2 U6.50 | length 63.5
  Top Layer w10: 3692.35,735.05 3686.89,729.6 U6.50@3686.89,703.17 3686.89,681.93 U6.50@3692.64,676.18
  other v1: 3708.22,667.05 3737.78,724.45 3185.57,2436.39 3215.57,2436.39
DMD_VOFS: C54.1 C500.1 C501.2 C511.1 C616.1 J1.5 J1.38 J1.76 R576.2 U6.49 | length 181
  Top Layer w10: C54.1@3667.21,609.81 U6.49@3667.21,703.17
  Top Layer w11.8: J1.76@2552.28,2393.7 v1(2552.28,2438.69) ; J1.5@3949.92,2393.7 v1(3949.92,2436.39)
  other v1: 3344.38,2438.69 3374.38,2438.69 2552.28,2468.69 3949.92,2471.72
  other v4: 3577.37,584.91 3577.37,612.94
DMD_VRST: C53.1 C503.1 C613.1 D6.2 J1.39 R57.1 R577.2 R578.2 U6.51 | length 320.5
  Top Layer w11: v4(3710.3,770.1) U6.51@3753.82,770.1
  Top Layer w20: v1(4260.99,720.37) R57.1@4285.15,720.37
  Bottom Layer w6.3: v1@3280.63,2438.69 C503.1@3280.63,2477.42
  Bottom Layer w20: v1(4163.8,550.74) R577.2@4205.39,550.74 C613.1@4301.12,550.74 4301.12,474.85 R578.2@4301.71,474.26
  other v1: 4205.34,518.47 4265.07,548.76 3249.63,2436.39 3279.63,2436.39
DMUX0: TP6.1 U6.40 | length 592
  Top Layer w6.3: v4(3490.04,658.64) U6.40@3490.04,703.17
  SIGNAL 4 w4.5: TP6.1@3005.3,615.56 3037.24,583.62 3303.92,583.62 3401.21,680.9 3467.78,680.9 v4(3490.04,658.64)
DMUX1: TP13.1 U6.41 | length 717.8
  Top Layer w6.3: U6.41@3509.73,703.17 v4(3509.73,747.7)
  SIGNAL 4 w4.5: TP13.1@3005.3,474.4 3101.76,570.86 3382.32,570.86 3446.85,635.39 3492.42,635.39 3509.73,652.69 v4(3509.73,747.7)
DRST_HS: C611.1 D6.1 L8.1 U6.54 | length 609.7
  Top Layer w11: U6.54@3753.82,829.15 3796.99,829.15 3821.23,804.91 3821.23,783.42 3830.82,773.82
  Top Layer w15: 3830.82,773.82 3853.64,751 3863.46,751 3922.12,692.34 L8.1@4004.88,692.34 4146.45,692.34 4159.12,679.67 D6.1@4205.39,679.67 v1(4205.39,721.49)
  Bottom Layer w15: C611.1@4205.39,679.67 v1(4205.39,721.49)
DRST_LS: C607.1 L8.2 U6.52 | length 491.6
  Top Layer w10: U6.52@3753.82,789.78 v4(3798.35,789.78) 3804.46,783.67 3804.46,749.18
  Top Layer w15: 3804.46,749.18 3804.46,648.38 3888.37,564.48 3888.37,563.77 3923.19,528.95 L8.2@4004.88,528.95
  Bottom Layer w11: C607.1@3753.82,809.78 3778.35,809.78 v4(3798.35,789.78)
DRST_SB: C611.2 R577.1 | length 50.2
  Bottom Layer w6.3: R577.1@4205.39,597.98 C611.2@4205.39,648.18
DVI_5V: C522.1 J4.18 R507.2 R518.2 U503.8 | length 146.4
  Top Layer w11.81: 367.53,2031.87 381.23,2018.16 J4.18@451.18,2018.16
  Bottom Layer w11.81: U503.8@192.57,1920.84 215.54,1920.84
  Bottom Layer w23.6: R507.2@257.96,2043.27 v1(257.96,2077.32)
  other v1: 226.98,1855.91 257.96,1855.91 224.85,1907.32
EXT_RES: R515.1 U501.96 | length 147.7
  Bottom Layer w6.3: R515.1@778.46,1953.52 782.4,1953.52 810.52,1981.65 864.31,1981.65 870.16,1975.8 U501.96@912.1,1975.8
FAN_PWM: C56.2 J14.1 R64.2 | length 174.6
  Top Layer w6.3: R64.2@2801.43,442.96 C56.2@2854.5,442.96 2854.5,343.7 J14.1@2838.75,327.95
